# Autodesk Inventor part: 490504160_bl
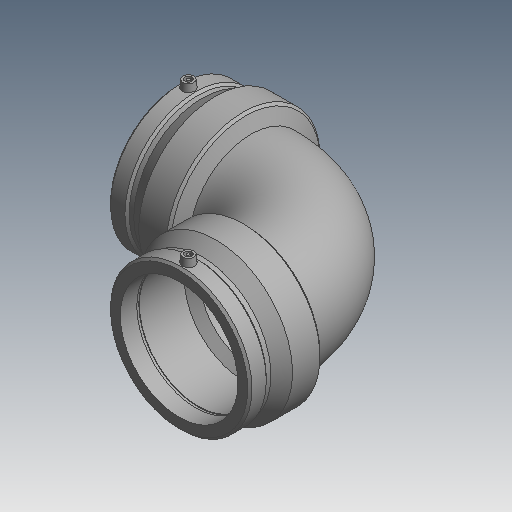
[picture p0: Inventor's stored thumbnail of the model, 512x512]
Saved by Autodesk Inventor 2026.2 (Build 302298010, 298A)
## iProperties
Created: 2017-06
Part Number: 490504160_bl
Material: Generic
Description: PLASSON 90° ELBOW 160
Document SubType Name: Modeling
Designer: KIM
Mass: 55.0731 g
Surface Area: 148.067 cm^2
Volume: 55.0731 cm^3
Density: 1 g/cm^3
Appearance: Default
Author: KIM
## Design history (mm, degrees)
derived "490504.ipt"
feature "Solid1::490504.ipt" dims "ScaleForDerivedMember" = 10
tag "TaggingFeature1"
body "Solid1"
other parameters: "d2" = 209 [user parameter], "d4" = 80.75 [user parameter], "d5" = 188.1 [user parameter], "d8" = 168 deg [user parameter], "d10" = 34.8 [user parameter], "d11" = 11.6 [user parameter], "d14" = 17.6296 [user parameter], "d19" = 3.52592 [user parameter], "d20" = 168 deg [user parameter], "d22" = 192.28 [user parameter], "d23" = 209 [user parameter], "d24" = 186.5116 [user parameter], "d29" = 106 [user parameter], "d30" = 15 [user parameter], "d31" = 113.05 [user parameter], "d34" = 5 deg [user parameter], "d35" = 15 [user parameter], "d39" = 5 deg [user parameter], "d41" = 4 [user parameter], "d42" = 14 [user parameter], "d43" = 0 [user parameter], "d45" = 4 [user parameter], "d46" = 14 [user parameter], "d47" = 0 [user parameter], "d50" = 136 [user parameter], "d51" = 34.8 [user parameter], "d52" = 87 [user parameter], "d54" = 90 deg [user parameter], "d67" = 45 deg [user parameter], "d71" = 90 deg [user parameter], "d75" = 10.45 [user parameter], "d82" = 45 deg [user parameter], "d83" = 87 [user parameter], "d84" = 188.1 [user parameter], "d87" = 90 deg [user parameter], "d90" = 87 [user parameter], "d91" = 0 [user parameter], "d92" = 87 [user parameter], "d93" = 0 [user parameter], "d94" = 90 deg [user parameter], "d101" = 3 [user parameter], "d102" = 0 [user parameter], "d103" = 3 [user parameter], "d104" = 0 [user parameter], "d105" = 25.23 [user parameter], "d106" = 6.3075 [user parameter], "d110" = 47.85 [user parameter], "d111" = 323 [user parameter], "d112" = 323 [user parameter], "d113" = 323 [user parameter], "d114" = 323 [user parameter], "L_" = 323 [user parameter], "L_1" = 87 [user parameter], "D_" = 209 [user parameter], "A_" = 106 [user parameter], "d_2" = 12 [user parameter]
